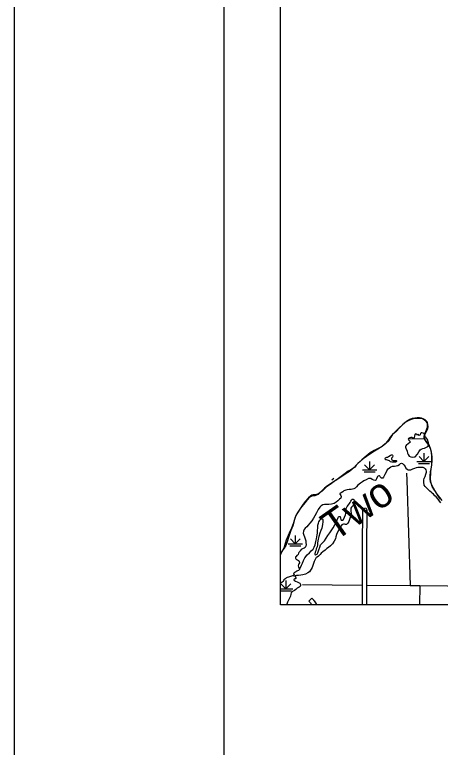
# Model space of a CAD drawing. Extents: x 1373094 to 1376427, y 1168361 to 1170494.
# Drawn here: x 1373093.7 to 1373345.9, y 1169551.7 to 1169986.1 of the extents above; entities that cross this region are included whole.
import ezdxf

# ---------------------------------------------------------------- set-up
doc = ezdxf.new("R2010")
doc.units = 0
for name, color, linetype in [('R_Axis', 7, 'Continuous'), ('R_Border', 7, 'Continuous'), ('R_No Plot', 7, 'Continuous')]:
    doc.layers.add(name, color=color, linetype=linetype)

msp = doc.modelspace()

# ---------------------------------------------------------------- linework, layer by layer
at = {"layer": 'R_Axis'}
for p, q in [((1373336.21, 1169726.16), (1373336.21, 1169721.16)), ((1373336.21, 1169721.16), (1373333.26, 1169724.1)), ((1373336.21, 1169721.16), (1373339.16, 1169724.1)), ((1373304.01, 1169716.23), (1373301.06, 1169719.17)), ((1373304.01, 1169721.23), (1373304.01, 1169716.23)), ((1373304.01, 1169716.23), (1373306.96, 1169719.17)), ((1373332.04, 1169721.16), (1373340.38, 1169721.16)), ((1373332.88, 1169720.02), (1373339.54, 1169720.02)), ((1373299.84, 1169716.23), (1373308.18, 1169716.23)), ((1373300.68, 1169715.09), (1373307.34, 1169715.09)), ((1373299.46, 1169692.92), (1373301.85, 1169693.68)), ((1373259.97, 1169672.36), (1373257.02, 1169675.3)), ((1373259.97, 1169677.36), (1373259.97, 1169672.36)), ((1373259.97, 1169672.36), (1373262.91, 1169675.3)), ((1373255.8, 1169672.36), (1373264.13, 1169672.36)), ((1373256.63, 1169671.22), (1373263.3, 1169671.22)), ((1373254.35, 1169645.63), (1373251.4, 1169648.58)), ((1373254.35, 1169650.63), (1373254.35, 1169645.63)), ((1373254.35, 1169645.63), (1373257.29, 1169648.58)), ((1373251.19, 1169645.63), (1373258.51, 1169645.63)), ((1373251.19, 1169644.5), (1373257.68, 1169644.5)), ((1373268.07, 1169638.27), (1373269.72, 1169640.15))]:
    msp.add_line(p, q, dxfattribs=at)
for points in [[(1373340.4, 1169716.72), (1373340.79, 1169719.06), (1373341.07, 1169721.76), (1373341.06, 1169723.9), (1373340.72, 1169726.67), (1373340.14, 1169728.94), (1373339.1, 1169731.37), (1373338.53, 1169732.3), (1373337.6, 1169733.16), (1373337.13, 1169733.76), (1373336.73, 1169734.53), (1373336.52, 1169735.29), (1373336.55, 1169736.03), (1373336.71, 1169737.1), (1373337.21, 1169738.17), (1373337.87, 1169739.27), (1373338.46, 1169740.68), (1373338.62, 1169741.81), (1373338.45, 1169743.08), (1373338.08, 1169744.11), (1373337.47, 1169744.91), (1373336.41, 1169745.84), (1373335.24, 1169746.4), (1373333.24, 1169746.69), (1373331.68, 1169746.72), (1373329.79, 1169746.47), (1373327.56, 1169745.7), (1373325.97, 1169744.95), (1373325.38, 1169744.55), (1373324.25, 1169743.67), (1373321.63, 1169741.22), (1373319.65, 1169739.01), (1373317.6, 1169737.1), (1373316.64, 1169735.66), (1373315.59, 1169733.58), (1373313.4, 1169731.7), (1373311.35, 1169730.15), (1373308.93, 1169728.51), (1373306.97, 1169727.29), (1373304.22, 1169725.48), (1373302.23, 1169724.2), (1373300.08, 1169722.82), (1373298.39, 1169721.21), (1373297.03, 1169719.93), (1373296.11, 1169718.96), (1373295.18, 1169717.82), (1373293.42, 1169716.61), (1373291.37, 1169715.36), (1373288.62, 1169713.38), (1373285.51, 1169711.06), (1373283.05, 1169709.38), (1373280.6, 1169707.53), (1373278.32, 1169705.88), (1373276.03, 1169703.83), (1373274.77, 1169702.69), (1373273.48, 1169701.58), (1373272.52, 1169701.14), (1373271.52, 1169700.87), (1373270.96, 1169700.77), (1373269.7, 1169700.53), (1373268.27, 1169699.82), (1373266.91, 1169698.48), (1373265.72, 1169696.77), (1373263.87, 1169694.39), (1373262.65, 1169692.94), (1373261.23, 1169690.77), (1373260.24, 1169688.96), (1373259.95, 1169688.22), (1373259.32, 1169686.22), (1373258.9, 1169684.31), (1373258.51, 1169683.04), (1373257.26, 1169680.26), (1373256.04, 1169676.75), (1373254.86, 1169672.98), (1373254.31, 1169671.44), (1373253.42, 1169669.76), (1373252.26, 1169668.22), (1373251.4, 1169666.81), (1373251.19, 1169666.04)], [(1373340.13, 1169715.11), (1373340.64, 1169717.89), (1373340.82, 1169719.26), (1373340.87, 1169720.2), (1373340.89, 1169721.47), (1373340.89, 1169722.43), (1373340.85, 1169723.52), (1373340.82, 1169724.55), (1373340.7, 1169726.37), (1373340.48, 1169727.5), (1373340.04, 1169728.89), (1373339.37, 1169730.16), (1373338.89, 1169730.89), (1373338.49, 1169731.57), (1373337.98, 1169732.36), (1373337.5, 1169733.07), (1373336.78, 1169734.12), (1373336.36, 1169735.18), (1373336.39, 1169736.22), (1373336.56, 1169737.07), (1373336.83, 1169737.99), (1373337.29, 1169739.05), (1373337.67, 1169739.99), (1373337.96, 1169740.77), (1373338.27, 1169741.61), (1373338.37, 1169742.43), (1373338.39, 1169743.18), (1373338.21, 1169744.28), (1373337.93, 1169744.87), (1373337.54, 1169745.35), (1373336.9, 1169745.8), (1373335.74, 1169746.47), (1373334.68, 1169746.8), (1373333.65, 1169746.98), (1373332.15, 1169747.07), (1373330.69, 1169746.92), (1373329.28, 1169746.65), (1373327.8, 1169746.07), (1373325.76, 1169744.94), (1373323.39, 1169742.9), (1373321.62, 1169741.25), (1373319.76, 1169739.34), (1373318.05, 1169737.78), (1373317.1, 1169736.86), (1373316.19, 1169735.54), (1373315.55, 1169734.59), (1373314.56, 1169733.21), (1373313.19, 1169731.6), (1373311.72, 1169730.35), (1373309.48, 1169729.04), (1373306.7, 1169727.59), (1373304.37, 1169726.21), (1373301.99, 1169724.41), (1373299.34, 1169722.18), (1373297.18, 1169720.14), (1373295.91, 1169718.74), (1373294.85, 1169717.57), (1373293.5, 1169716.36), (1373292.07, 1169715.3), (1373290.11, 1169714.06), (1373284.54, 1169710.3)], [(1373336.56, 1169737.07), (1373336.22, 1169737.73), (1373335.69, 1169738.05), (1373334.84, 1169738.18), (1373334.54, 1169738.15), (1373334.26, 1169737.98), (1373334.11, 1169737.71), (1373333.89, 1169737.02), (1373333.77, 1169736.8), (1373333.62, 1169736.69), (1373333.23, 1169736.64), (1373333.11, 1169736.67), (1373332.93, 1169736.77), (1373332.89, 1169737.14), (1373332.75, 1169737.31), (1373332.59, 1169737.27), (1373332.41, 1169737.06), (1373332.24, 1169736.95), (1373332.01, 1169736.93), (1373331.72, 1169737.2), (1373331.56, 1169737.61), (1373331.38, 1169737.73), (1373331.1, 1169737.63), (1373330.82, 1169737.22), (1373330.58, 1169736.16), (1373330.45, 1169735.44), (1373330.33, 1169735.21), (1373330.08, 1169735.03), (1373329.81, 1169735.01), (1373329.62, 1169735.07), (1373329.2, 1169735.36), (1373328.51, 1169735.35), (1373327.74, 1169735.15), (1373327.09, 1169734.82), (1373326.9, 1169734.43), (1373326.96, 1169734.06), (1373327.25, 1169733.72), (1373327.88, 1169733.2), (1373328.09, 1169732.89), (1373328.08, 1169732.59), (1373326.54, 1169731.43), (1373325.93, 1169731.01), (1373325.5, 1169730.55), (1373325.33, 1169730.06), (1373325.33, 1169729.59), (1373325.45, 1169729.09), (1373326.23, 1169727.22), (1373326.52, 1169726.13), (1373326.83, 1169725.23), (1373327.4, 1169724.31), (1373328.41, 1169723.85), (1373329.63, 1169723.75), (1373331.07, 1169724), (1373332.3, 1169725.49), (1373333.15, 1169726.92), (1373333.95, 1169727.99), (1373334.6, 1169728.52), (1373335.58, 1169728.8), (1373336.55, 1169729.17), (1373337.61, 1169729.59), (1373338.45, 1169730.03), (1373338.81, 1169730.75), (1373338.97, 1169731.69), (1373338.95, 1169732.3), (1373338.2, 1169734.17), (1373337.19, 1169735.87), (1373336.56, 1169737.07)], [(1373327.08, 1169734.81), (1373336.62, 1169734.53)], [(1373315.28, 1169724.05), (1373316.23, 1169724.7), (1373316.69, 1169725.02), (1373317.05, 1169725.14), (1373317.39, 1169725.1), (1373317.59, 1169724.89), (1373317.77, 1169724.44), (1373317.54, 1169723.78), (1373317.05, 1169723.19), (1373316.91, 1169722.78), (1373316.93, 1169722.46), (1373317.23, 1169722.17), (1373317.54, 1169722), (1373318.02, 1169721.84), (1373318.77, 1169721.79), (1373319.49, 1169721.73), (1373319.78, 1169721.7), (1373319.95, 1169721.62), (1373320, 1169721.53), (1373319.99, 1169721.36), (1373319.87, 1169721.16), (1373319.64, 1169720.96), (1373319.26, 1169720.82), (1373318.86, 1169720.78), (1373318.13, 1169720.74), (1373317.25, 1169720.77), (1373316.46, 1169720.95), (1373315.83, 1169721.47), (1373315.22, 1169721.82), (1373314.52, 1169721.97), (1373313.95, 1169722.07), (1373313.53, 1169722.25), (1373313.19, 1169722.55), (1373313.16, 1169722.97), (1373313.47, 1169723.43), (1373313.76, 1169723.6), (1373314.12, 1169723.71), (1373314.69, 1169723.76), (1373315.27, 1169724.04)], [(1373314.44, 1169716.06), (1373314.92, 1169716.84), (1373315.71, 1169717.46), (1373316.54, 1169717.92), (1373317.62, 1169718.3), (1373318.73, 1169718.39), (1373319.77, 1169718.53), (1373320.68, 1169718.83), (1373321.68, 1169719.47), (1373322.37, 1169719.95), (1373322.98, 1169720.17), (1373323.54, 1169719.92), (1373324.25, 1169719.23), (1373324.96, 1169718.11), (1373325.48, 1169717.27), (1373326.18, 1169716.64), (1373326.87, 1169716.32), (1373327.49, 1169716.22), (1373328.47, 1169716.31), (1373329.53, 1169716.72), (1373330.76, 1169717.21), (1373331.72, 1169717.55), (1373332.51, 1169717.75), (1373333.38, 1169717.89), (1373334.41, 1169717.9), (1373335.49, 1169717.8), (1373336.37, 1169717.42), (1373336.98, 1169716.88), (1373337.34, 1169716.3), (1373337.58, 1169715.44), (1373337.49, 1169714.57), (1373337.15, 1169713.54), (1373336.65, 1169712.09), (1373336.39, 1169711.35)], [(1373314.44, 1169716.06), (1373313.01, 1169713.41), (1373312.63, 1169712.62), (1373312.25, 1169711.89), (1373311.77, 1169711.34), (1373311.08, 1169711.38), (1373310.33, 1169712.09), (1373310.12, 1169712.42), (1373309.89, 1169712.65), (1373309.41, 1169712.71), (1373308.97, 1169712.48), (1373308.63, 1169712.18), (1373308.42, 1169711.83), (1373308.02, 1169710.83), (1373307.67, 1169710.17), (1373307.26, 1169709.93), (1373306.41, 1169710.05), (1373305.46, 1169710.55), (1373304.62, 1169711.01), (1373303.98, 1169711.15), (1373303.33, 1169711.01), (1373301.97, 1169710.39), (1373300.57, 1169709.64), (1373299.74, 1169709.1), (1373298.66, 1169708.35), (1373297.71, 1169707.74), (1373296.93, 1169707.04), (1373296.28, 1169706.14), (1373295.49, 1169705.33), (1373294.67, 1169704.91), (1373293.11, 1169704.65), (1373291.89, 1169704.57), (1373290.68, 1169704.44), (1373289.81, 1169704.22), (1373288.74, 1169703.72), (1373288.05, 1169703.27), (1373287.17, 1169702.63), (1373286.58, 1169702.21), (1373286.27, 1169701.9), (1373286.26, 1169701.74), (1373286.59, 1169701.51), (1373287, 1169701.1), (1373287.17, 1169700.32), (1373286.85, 1169699.49), (1373286.16, 1169698.77), (1373285.15, 1169697.91), (1373284.23, 1169697.12), (1373283.05, 1169696.35), (1373281.35, 1169695.79), (1373279.85, 1169695.66), (1373278.34, 1169695.6), (1373277.29, 1169695.57), (1373276.34, 1169695.48), (1373275.37, 1169694.97), (1373274.46, 1169694.06), (1373273.52, 1169692.62), (1373272.53, 1169690.81), (1373271.56, 1169688.99), (1373270.72, 1169687.52), (1373269.69, 1169686.02), (1373268.61, 1169684.67), (1373267.58, 1169683.39), (1373266.8, 1169682.43), (1373265.89, 1169681.54), (1373265.23, 1169680.82), (1373264.78, 1169679.88), (1373264.63, 1169678.67), (1373264.96, 1169677.51), (1373265.37, 1169676.4), (1373265.72, 1169675.35), (1373266.11, 1169674.06), (1373266.28, 1169672.94), (1373266.3, 1169671.94), (1373266.17, 1169671.05), (1373265.74, 1169670.25), (1373265.17, 1169669.77), (1373264.2, 1169669.31), (1373263.46, 1169668.89), (1373262.91, 1169668.29), (1373262.56, 1169667.73), (1373262.07, 1169667.25), (1373261.88, 1169666.86), (1373261.65, 1169666.1), (1373261.21, 1169665.71), (1373260.82, 1169665.45), (1373260.44, 1169664.92), (1373260.16, 1169664.54), (1373260.13, 1169663.89), (1373260.31, 1169663.39), (1373260.72, 1169663.09), (1373261.27, 1169662.83), (1373261.83, 1169662.53), (1373262.29, 1169662.02), (1373262.4, 1169661.16), (1373262.08, 1169660.45), (1373261.87, 1169660.04), (1373261.71, 1169659.35), (1373261.79, 1169658.58), (1373262.07, 1169658.04), (1373262.37, 1169657.59)], [(1373325.9, 1169714.25), (1373326.04, 1169710.18)], [(1373346.03, 1169698.75), (1373345.08, 1169700.25), (1373343.69, 1169702.29), (1373342.58, 1169703.96), (1373341.77, 1169705.26), (1373341.17, 1169706.52), (1373340.66, 1169707.63), (1373340.1, 1169709.2), (1373339.78, 1169710.9), (1373339.82, 1169712.65), (1373340.13, 1169715.11)], [(1373346.97, 1169697.99), (1373345.53, 1169699.72), (1373343.93, 1169701.75), (1373343.02, 1169703.31), (1373342.02, 1169704.81), (1373341.11, 1169706.34), (1373340.61, 1169707.67), (1373340.2, 1169709.38), (1373339.99, 1169710.61), (1373340.17, 1169714.82), (1373340.4, 1169716.72)], [(1373284.54, 1169710.3), (1373282.62, 1169709.15), (1373280.89, 1169707.94), (1373279.09, 1169706.75), (1373277.34, 1169705.26), (1373276.16, 1169704.19), (1373275.41, 1169703.48), (1373274.45, 1169702.61), (1373273.32, 1169701.83), (1373272.46, 1169701.55), (1373271.63, 1169701.43), (1373270.6, 1169701.32), (1373269.72, 1169701.13), (1373269.05, 1169700.7), (1373267.83, 1169699.65), (1373265.72, 1169697.47), (1373264.13, 1169695.26), (1373263.01, 1169693.51), (1373261.54, 1169691.15), (1373260.34, 1169689.14), (1373259.63, 1169687.45), (1373259.33, 1169686.24), (1373258.73, 1169684.15), (1373257.7, 1169681.72), (1373256.73, 1169679.64), (1373255.66, 1169677.25), (1373254.63, 1169674.59), (1373254, 1169672.55), (1373253.34, 1169670.46), (1373252.54, 1169668.88), (1373251.96, 1169667.75), (1373251.27, 1169666.09), (1373251.19, 1169665.88)], [(1373281.66, 1169710.23), (1373282.84, 1169711.26)], [(1373326.04, 1169710.18), (1373327.98, 1169647.62)], [(1373346.23, 1169696.75), (1373345.46, 1169697.72), (1373344.53, 1169698.83), (1373343.35, 1169700.17), (1373342.66, 1169700.89), (1373341.79, 1169701.75), (1373341.14, 1169702.34), (1373340.44, 1169702.99), (1373339.65, 1169703.66), (1373338.86, 1169704.29), (1373338.23, 1169704.91), (1373337.67, 1169705.49), (1373336.93, 1169706.43), (1373336.39, 1169707.12), (1373336.05, 1169708.93), (1373336.1, 1169710.09), (1373336.39, 1169711.35)], [(1373262.37, 1169657.59), (1373262.91, 1169658.01), (1373263.58, 1169659.6), (1373264.13, 1169660.87), (1373264.87, 1169662.52), (1373265.65, 1169663.98), (1373266.97, 1169665.79), (1373268.29, 1169667.02), (1373269.43, 1169668.14), (1373270.45, 1169669.27), (1373271.08, 1169670.45), (1373271.66, 1169671.84), (1373272.18, 1169673.66), (1373272.56, 1169675.31), (1373272.92, 1169677.61), (1373273.02, 1169678.66), (1373273.16, 1169680.41), (1373273.23, 1169681.73), (1373273.37, 1169683.35), (1373273.62, 1169684.66), (1373273.87, 1169685.37), (1373274.2, 1169686.05), (1373274.78, 1169686.82), (1373275.34, 1169687.15), (1373276.05, 1169687.15), (1373276.28, 1169686.77), (1373276.27, 1169685.3), (1373276.07, 1169683.77), (1373275.68, 1169681.69), (1373275.1, 1169680.24), (1373274.44, 1169678.6), (1373273.9, 1169676.73), (1373273.56, 1169675.03), (1373273.2, 1169672.98), (1373273.05, 1169671.69), (1373272.85, 1169670.53), (1373272.41, 1169669.32), (1373272.04, 1169668.29), (1373271.76, 1169667.4), (1373271.62, 1169666.47), (1373271.73, 1169665.77), (1373271.87, 1169665.76), (1373272.86, 1169666.15), (1373273.37, 1169666.93), (1373273.97, 1169668.86), (1373274.42, 1169670.27), (1373274.93, 1169671.71), (1373276.01, 1169672.95), (1373277.25, 1169674.14), (1373278.26, 1169675.65), (1373279.28, 1169677.3), (1373280.33, 1169678.78), (1373281.52, 1169680.55), (1373282.36, 1169681.86), (1373283.3, 1169683.52), (1373284, 1169684.79), (1373284.74, 1169686.5), (1373285.14, 1169687.43), (1373285.27, 1169687.88), (1373285.48, 1169688.29), (1373285.76, 1169688.6), (1373286.1, 1169688.64), (1373286.48, 1169688.48), (1373286.65, 1169687.6), (1373286.92, 1169686.72), (1373287.18, 1169686.44), (1373287.88, 1169686.43), (1373288.43, 1169686.81), (1373289.17, 1169688.07), (1373289.68, 1169689.47), (1373289.83, 1169690.29), (1373289.81, 1169691.63), (1373290.01, 1169692.99), (1373290.29, 1169693.78), (1373290.7, 1169694.53), (1373291.46, 1169695.45), (1373292.1, 1169696.32), (1373292.54, 1169696.83), (1373292.95, 1169697.66), (1373293.3, 1169698.32), (1373293.48, 1169698.61), (1373293.75, 1169698.83), (1373294.29, 1169698.85), (1373294.57, 1169698.64), (1373294.82, 1169697.61), (1373294.96, 1169696.56), (1373294.64, 1169695.56), (1373293.97, 1169694.81), (1373293.29, 1169694.14), (1373292.81, 1169693.41), (1373292.81, 1169692), (1373293.12, 1169690.42), (1373293.03, 1169689.15), (1373292.52, 1169687.93), (1373292.06, 1169686.87), (1373291.63, 1169685.54), (1373291.17, 1169684.54), (1373290.34, 1169683.78), (1373289.67, 1169683.8), (1373289.02, 1169683.92), (1373288.49, 1169683.99)], [(1373299.46, 1169692.92), (1373299.7, 1169692.19), (1373299.83, 1169691.8), (1373299.86, 1169691.68), (1373299.87, 1169691.56), (1373299.87, 1169687.37), (1373299.79, 1169684.6)], [(1373301.85, 1169693.68), (1373302.07, 1169692.98), (1373302.25, 1169692.47), (1373302.34, 1169692.02), (1373302.37, 1169691.65), (1373302.37, 1169687.34), (1373302.29, 1169684.54)], [(1373288.49, 1169683.99), (1373287.89, 1169683.9), (1373287.56, 1169683.65), (1373286.63, 1169682.32), (1373285.69, 1169680.71), (1373284.96, 1169679.28), (1373284.35, 1169677.9), (1373283.98, 1169676.42), (1373283.68, 1169675.27), (1373283.02, 1169673.83), (1373281.99, 1169672.4), (1373280.75, 1169671.17), (1373279.55, 1169670.13), (1373278.68, 1169669.49), (1373277.6, 1169668.65), (1373276.31, 1169667.66), (1373275.29, 1169666.72), (1373274.61, 1169665.95), (1373273.77, 1169664.99), (1373272.93, 1169664.47), (1373272.34, 1169664.17), (1373271.91, 1169663.52), (1373271.2, 1169661.86), (1373270.73, 1169660.6), (1373270.43, 1169659.47), (1373270.04, 1169658.29), (1373268.31, 1169655.8), (1373267.31, 1169655.08), (1373265.93, 1169654.44), (1373264.44, 1169654), (1373263.2, 1169653.82), (1373261.87, 1169653.65), (1373261.27, 1169653.57), (1373260.68, 1169653.49), (1373259.82, 1169653.4)], [(1373299.79, 1169684.6), (1373299.63, 1169678.4), (1373299.64, 1169675.77)], [(1373302.29, 1169684.54), (1373302.13, 1169678.38), (1373302.14, 1169675.78)], [(1373299.64, 1169675.77), (1373299.67, 1169670.94), (1373299.64, 1169666.98)], [(1373302.14, 1169675.78), (1373302.17, 1169670.93), (1373302.14, 1169666.96)], [(1373299.64, 1169666.98), (1373299.58, 1169658.18)], [(1373302.14, 1169666.96), (1373302.08, 1169658.16)], [(1373262.37, 1169657.59), (1373262.36, 1169657.13), (1373262.11, 1169656.77), (1373261.76, 1169656.49), (1373261.32, 1169656.26), (1373260.79, 1169656.07), (1373260.29, 1169655.75), (1373260.01, 1169655.64), (1373259.58, 1169655.36), (1373258.87, 1169654.84), (1373258.83, 1169654.76), (1373258.85, 1169654.68), (1373259.2, 1169654.42), (1373259.23, 1169654.24), (1373259.12, 1169654.02), (1373258.91, 1169653.81), (1373258.82, 1169653.61), (1373258.83, 1169653.52), (1373258.9, 1169653.46), (1373258.99, 1169653.42), (1373259.15, 1169653.42), (1373259.69, 1169653.45), (1373259.82, 1169653.4)], [(1373262.37, 1169657.59), (1373262.36, 1169657.13), (1373262.11, 1169656.77), (1373261.76, 1169656.49), (1373261.32, 1169656.26), (1373260.79, 1169656.07), (1373260.29, 1169655.75), (1373260.01, 1169655.64), (1373259.58, 1169655.36), (1373258.87, 1169654.84), (1373258.83, 1169654.76), (1373258.85, 1169654.68), (1373259.2, 1169654.42), (1373259.23, 1169654.24), (1373259.12, 1169654.02), (1373258.91, 1169653.81), (1373258.82, 1169653.61), (1373258.83, 1169653.52), (1373258.9, 1169653.46), (1373258.99, 1169653.42), (1373259.15, 1169653.42), (1373259.69, 1169653.45), (1373259.82, 1169653.4)], [(1373299.58, 1169658.18), (1373299.58, 1169658.05), (1373299.59, 1169649.37)], [(1373302.08, 1169658.16), (1373302.08, 1169658.04), (1373302.09, 1169649.37)], [(1373258.83, 1169653.52), (1373257.14, 1169652.99), (1373255.91, 1169652.58), (1373255.16, 1169652.44), (1373254.8, 1169652.26), (1373254.46, 1169652.02), (1373254.11, 1169651.74), (1373253.7, 1169651.33), (1373253.24, 1169650.9), (1373253.03, 1169650.48), (1373252.84, 1169650.11), (1373252.76, 1169650.01), (1373252.43, 1169649.82), (1373252.25, 1169649.57), (1373252.07, 1169649.48), (1373251.77, 1169649.39), (1373251.55, 1169649.34), (1373251.32, 1169649.23), (1373251.19, 1169649.15)], [(1373259.82, 1169653.4), (1373259.94, 1169653.28), (1373260.05, 1169653.07), (1373260.12, 1169652.81), (1373260.24, 1169652.22), (1373260.23, 1169651.85), (1373260.12, 1169651.65), (1373259.59, 1169651.52), (1373259.23, 1169651.35), (1373259.15, 1169651.09), (1373259.18, 1169650.81), (1373259.47, 1169650.55), (1373260.14, 1169650.15), (1373261.04, 1169649.79), (1373261.89, 1169649.39), (1373262.59, 1169648.97), (1373263.04, 1169648.28), (1373263.07, 1169647.66), (1373262.75, 1169647.02), (1373262.17, 1169646.57), (1373261.16, 1169646.06), (1373260.32, 1169645.32), (1373259.54, 1169644.58), (1373258.33, 1169644.03), (1373257.5, 1169643.38), (1373257.26, 1169642.4), (1373257.04, 1169641.22), (1373256.54, 1169640.11), (1373255.95, 1169638.99), (1373255.4, 1169637.67), (1373254.88, 1169636.49), (1373254.72, 1169636.22)], [(1373264.16, 1169648.26), (1373299.36, 1169647.91)], [(1373299.59, 1169649.37), (1373299.61, 1169640.57)], [(1373302.09, 1169649.37), (1373302.11, 1169640.57)], [(1373302.28, 1169647.88), (1373327.98, 1169647.62), (1373333.66, 1169647.56), (1373415.32, 1169646.62), (1373417.14, 1169646.61)], [(1373333.66, 1169647.56), (1373333.63, 1169636.22)], [(1373269.72, 1169640.15), (1373270.1, 1169639.82), (1373270.66, 1169639.23), (1373270.82, 1169639.03), (1373271.23, 1169638.57), (1373271.62, 1169638), (1373271.98, 1169637.42), (1373272.27, 1169636.68), (1373272.36, 1169636.39), (1373272.41, 1169636.22)], [(1373299.61, 1169640.57), (1373299.61, 1169639.15), (1373299.6, 1169636.22)], [(1373302.11, 1169640.57), (1373302.11, 1169639.15), (1373302.1, 1169636.22)], [(1373268.07, 1169638.27), (1373268.37, 1169638.01), (1373268.75, 1169637.61), (1373268.88, 1169637.45), (1373269.26, 1169637.02), (1373269.53, 1169636.63), (1373269.73, 1169636.3), (1373269.76, 1169636.22)]]:
    msp.add_lwpolyline(points, dxfattribs=at)
at = {"layer": 'R_Border'}
msp.add_line((1373217.75, 1168400.82), (1373217.75, 1170455.42), dxfattribs=at)
at = {"layer": 'R_No Plot'}
for points in [[(1373093.67, 1170494.36), (1376427.07, 1170494.36), (1376427.07, 1168360.99), (1373093.67, 1168360.99)], [(1373251.19, 1170420.71), (1373980.59, 1170420.71), (1373980.59, 1169636.22), (1373251.19, 1169636.22)]]:
    msp.add_lwpolyline(points, close=True, dxfattribs=at)

# ---------------------------------------------------------------- texts
at = {"layer": 'R_Axis'}
msp.add_text('Two', height=17.6, rotation=35, dxfattribs=at).set_placement((1373283.43, 1169673.41))

doc.saveas('drawing.dxf')
